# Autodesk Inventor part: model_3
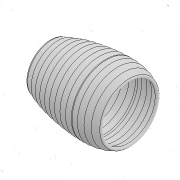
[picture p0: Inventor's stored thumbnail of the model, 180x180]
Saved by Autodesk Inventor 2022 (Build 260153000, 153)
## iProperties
Created: 2021-05
Part Number: model_3
Material: Všeobecné
Document SubType Name: Modeling
Designer: krejc
Density: 1 g/cm^3
Appearance: Výchozí
Mass: 215.66 g
Surface Area: 882.514 cm^2
Volume: 215.66 cm^3
Author: krejc
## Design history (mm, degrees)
sketch "profil"
  geometry: L1 (0, 0)-(0, 60); L2 (-135, 0)-(-135, 56.25); L3 (-133.574, 39.757)-(-132.5, 37.5); L4 (-132.5, 37.5)-(-131.426, 35.243); L5 (-1.407, 49.748)-(-2.5, 47.5); L6 (-2.5, 47.5)-(-3.593, 45.252); L7 (-4.041, 42.477)-(-4.045, 42.469); L8 (-3.593, 45.252)-(-3.593, 0); L9 (-13.593, 0)-(-13.593, 49.245); L10 (-23.593, 0)-(-23.593, 51.47); L11 (-33.593, 0)-(-33.593, 52.374); L12 (-43.593, 0)-(-43.593, 52.458); L13 (-53.593, 0)-(-53.593, 52.015); L14 (-63.593, 0)-(-63.593, 51.188); L15 (-73.593, 0)-(-73.593, 50.037); L16 (-83.593, 0)-(-83.593, 48.574); L17 (-93.593, 0)-(-93.593, 46.778); L18 (-103.593, 0)-(-103.593, 44.593); L19 (-113.593, 0)-(-113.593, 41.915); L20 (-123.593, 0)-(-123.593, 38.562); L21 (-131.426, 35.243)-(-131.426, 0); L22 (-40, 52.5)-(-40, 0); L23 (-1.407, 49.748)-(-1.407, 0); L24 (-11.407, 0)-(-11.407, 53.8); L25 (-21.407, 0)-(-21.407, 56.182); L26 (-31.407, 0)-(-31.407, 57.262); L27 (-41.407, 0)-(-41.407, 57.494); L28 (-51.407, 0)-(-51.407, 57.169); L29 (-61.407, 0)-(-61.407, 56.44); L30 (-71.407, 0)-(-71.407, 55.376); L31 (-40, 52.5)-(-40, 57.5); L32 (-81.407, 0)-(-81.407, 54.002); L33 (-91.407, 0)-(-91.407, 52.305); L34 (-101.407, 0)-(-101.407, 50.245); L35 (-111.407, 0)-(-111.407, 47.743); L36 (-121.407, 0)-(-121.407, 44.663); L37 (-131.407, 0)-(-131.407, 40.756); L38 (-133.574, 39.757)-(-133.574, 0); L39 (-3.593, 45.252)-(-13.593, 49.245); L40 (-13.593, 49.245)-(-23.593, 51.47); L41 (-23.593, 51.47)-(-33.593, 52.374); L42 (-33.593, 52.374)-(-40, 52.5); L43 (-40, 52.5)-(-43.593, 52.458); L44 (-43.593, 52.458)-(-53.593, 52.015); L45 (-53.593, 52.015)-(-63.593, 51.188); L46 (-63.593, 51.188)-(-73.593, 50.037); L47 (-73.593, 50.037)-(-83.593, 48.574); L48 (-103.593, 44.593)-(-113.593, 41.915); L49 (-113.593, 41.915)-(-123.593, 38.562); L50 (-123.593, 38.562)-(-131.426, 35.243); L51 (-83.593, 48.574)-(-93.593, 46.778); L52 (-93.593, 46.778)-(-103.593, 44.593); L53 (-11.407, 53.8)-(-21.407, 56.182); L54 (-21.407, 56.182)-(-31.407, 57.262); L55 (-31.407, 57.262)-(-40, 57.5); L56 (-40, 57.5)-(-41.407, 57.494); L57 (-41.407, 57.494)-(-51.407, 57.169); L58 (-51.407, 57.169)-(-61.407, 56.44); L59 (-61.407, 56.44)-(-71.407, 55.376); L60 (-71.407, 55.376)-(-81.407, 54.002); L61 (-81.407, 54.002)-(-91.407, 52.305); L62 (-91.407, 52.305)-(-101.407, 50.245); L63 (-101.407, 50.245)-(-111.407, 47.743); L64 (-111.407, 47.743)-(-121.407, 44.663)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; A1 r 2.5 centre (-2.5, 47.5) between (-1.407, 49.748) and (-3.593, 45.252); A2 r 2.5 centre (-132.5, 37.5) between (-133.574, 39.757) and (-131.426, 35.243); A3 r 2.5 centre (-2.5, 47.5) between (-3.593, 45.252) and (-1.407, 49.748); A4 r 2.5 centre (-132.5, 37.5) between (-133.574, 39.757) and (-131.426, 35.243)
  constraints: 134 end point, 25 vertical, 8 point on circle, 7 parallel, 4 centre point, 2 coincident, 2 point on line, 2 tangent, 68 other
  dimensions: "d0" = 5 diameter of A1; "d1" = 5 diameter of A2; "d2" = 95 dimension on L5.end; "d4" = 75 dimension on L3.end; "d5" = 130 horizontal distance of L5.end L3.end; "d9" = 40 horizontal distance of L1.start L31.end; "d11" = 115 dimension on L31.end; "d16" = 135 distance between parallel lines of L1 L2 (derived); "d64" = 10 distance between parallel lines of L9 L8; "d65" = 5 distance of L31.end L22.start; "d66" = 10 distance between parallel lines of L10 L9; "d67" = 10 distance between parallel lines of L10 L11; "d69" = 10 distance between parallel lines of L12 L13; "d70" = 10 distance between parallel lines of L14 L13; "d71" = 10 distance between parallel lines of L15 L14; "d72" = 10 distance between parallel lines of L16 L15; "d76" = 10 distance between parallel lines of L17 L16; "d77" = 10 distance between parallel lines of L18 L17; "d78" = 10 distance between parallel lines of L19 L18; "d79" = 10 distance between parallel lines of L20 L19; "d80" = 7.83266 distance between parallel lines of L21 L20; "d81" = 6.40704 distance between parallel lines of L11 L22; "d82" = 3.59296 distance between parallel lines of L12 L22; "d83" = 10 distance between parallel lines of L24 L23; "d84" = 10 distance between parallel lines of L25 L24; "d85" = 10 distance between parallel lines of L26 L25; "d86" = 3.59296 distance between parallel lines of L1 L8; "d87" = 1.40704 distance between parallel lines of L1 L23 (derived); "d89" = 10 distance between parallel lines of L28 L27; "d90" = 10 distance between parallel lines of L29 L28; "d91" = 10 distance between parallel lines of L30 L29; "d92" = 8.59296 distance from line of L26 L31.end (derived); "d93" = 1.40704 distance from line of L27 L31.end; "d94" = 10 distance between parallel lines of L32 L30; "d95" = 10 distance between parallel lines of L33 L32; "d96" = 10 distance between parallel lines of L34 L33; "d97" = 10 distance between parallel lines of L35 L34; "d98" = 10 distance between parallel lines of L36 L35; "d99" = 10 distance between parallel lines of L36 L37; "d100" = 2.16734 distance between parallel lines of L38 L37 (derived)
revolve "Rotace1" sketch "profil" stored, may be unused: angle "d14" = 360 deg
feature "Rozdělit1"
node "Těleso1"
